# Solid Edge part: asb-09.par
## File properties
Author: nakano
Template: iso metric part.par
Last saved by: nakano
Revision: 7
Application: Solid Edge
Density: 2517.84966844527 kg/m^3
Accuracy: 0.990
Username: nakano
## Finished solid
Body 1: solid body, 29 faces, 66 edges, 24 vertices.
  Faces by surface: cylinder 21, plane 8
  Edges by curve: circle 42, line 24
Bounding box of the edges (mm): 52.248 x 40.869 x 24.613, from (-26.1239, 0, -12.3063) to (26.1239, 40.8686, 12.3063).
Cylindrical faces by radius (mm): R0.254 x2, R1.1938 x12, R1.778 x2, R4.0005 x3, R12.3063 x2
Planar faces by outward normal: +x 2, +y 1, +z 1, -x 2, -y 1, -z 1
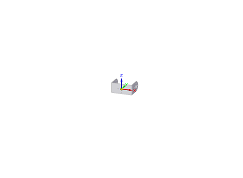
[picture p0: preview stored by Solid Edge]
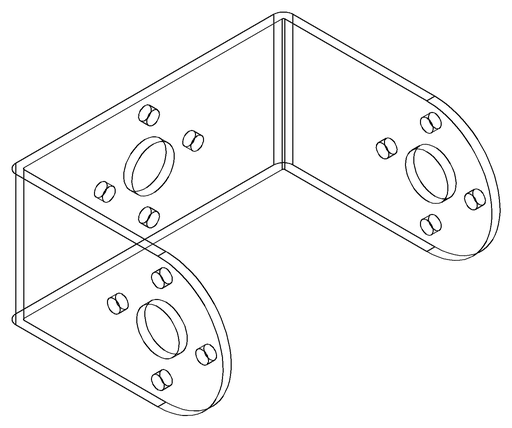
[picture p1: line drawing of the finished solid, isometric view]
